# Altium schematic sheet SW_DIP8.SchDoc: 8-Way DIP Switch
size A4; CheckedBy: D-820-0017; Author: NB2HND01; DrawnBy: SRKH; Engineer: SHOWELL; DocumentNumber: 14; SheetNumber: 14; SheetTotal: 14; PageSetup: Record=PageOptions|CenterHorizontal=True|CenterVertical=True|PrintScale=0.97|XCorrection=1.00|YCorrection=1.00|PrintKind=0|BorderSize=5000000|LeftOffset=0|BottomOffset=0|Orientation=2|PaperLength=1000|PaperWidth=1000|Scale=100|PaperSource=7|PrintQuality=-4|MediaType=1|DitherType=10|PaperKind=A4|PrintScaleMode=1
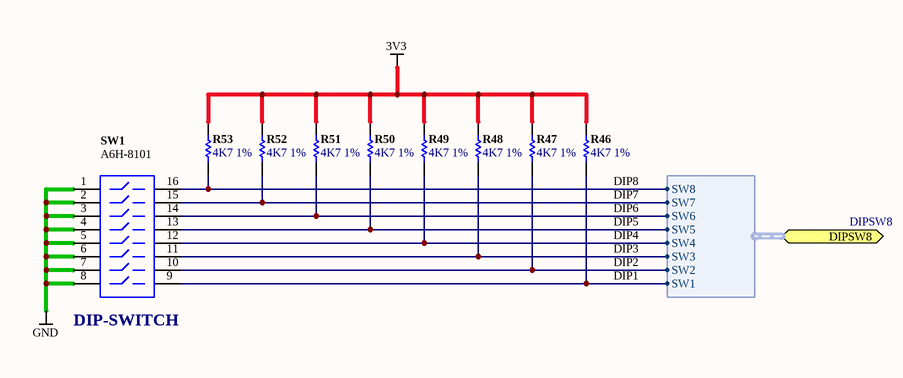
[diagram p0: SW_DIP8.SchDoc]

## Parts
R46  4K7 1%  [RESC1005-STAR]
R47  4K7 1%  [RESC1005-STAR]
R48  4K7 1%  [RESC1005-STAR]
R49  4K7 1%  [RESC1005-STAR]
R50  4K7 1%  [RESC1005-STAR]
R51  4K7 1%  [RESC1005-STAR]
R52  4K7 1%  [RESC1005-STAR]
R53  4K7 1%  [RESC1005-STAR]
SW1  A6H-8101  [A6H-8]

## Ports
DIPSW8 (harness DIPSW8)

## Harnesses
DIPSW8: SW8, SW7, SW6, SW5, SW4, SW3, SW2, SW1

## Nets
3V3: R46.2 R47.2 R48.2 R49.2 R50.2 R51.2 R52.2 R53.2
GND: SW1.1 SW1.2 SW1.3 SW1.4 SW1.5 SW1.6 SW1.7 SW1.8
DIP1: R46.1 SW1.9 ; port DIPSW8.SW1
DIP2: R47.1 SW1.10 ; port DIPSW8.SW2
DIP3: R48.1 SW1.11 ; port DIPSW8.SW3
DIP4: R49.1 SW1.12 ; port DIPSW8.SW4
DIP5: R50.1 SW1.13 ; port DIPSW8.SW5
DIP6: R51.1 SW1.14 ; port DIPSW8.SW6
DIP7: R52.1 SW1.15 ; port DIPSW8.SW7
DIP8: R53.1 SW1.16 ; port DIPSW8.SW8

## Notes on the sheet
- (near SW1) DIP-SWITCH

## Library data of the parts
R46-R53 = D-100-0088: Resistor, 4K7 1% 0402 (1005); Power Rating: 63 mW; Resistance: 4.7 K
SW1 = D-301-0009: Half-Pitch Dip-Switch  8-way; Rated Voltage: mV; Switch Type: SPDT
